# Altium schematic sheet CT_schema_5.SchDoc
size 297 x 173 mm
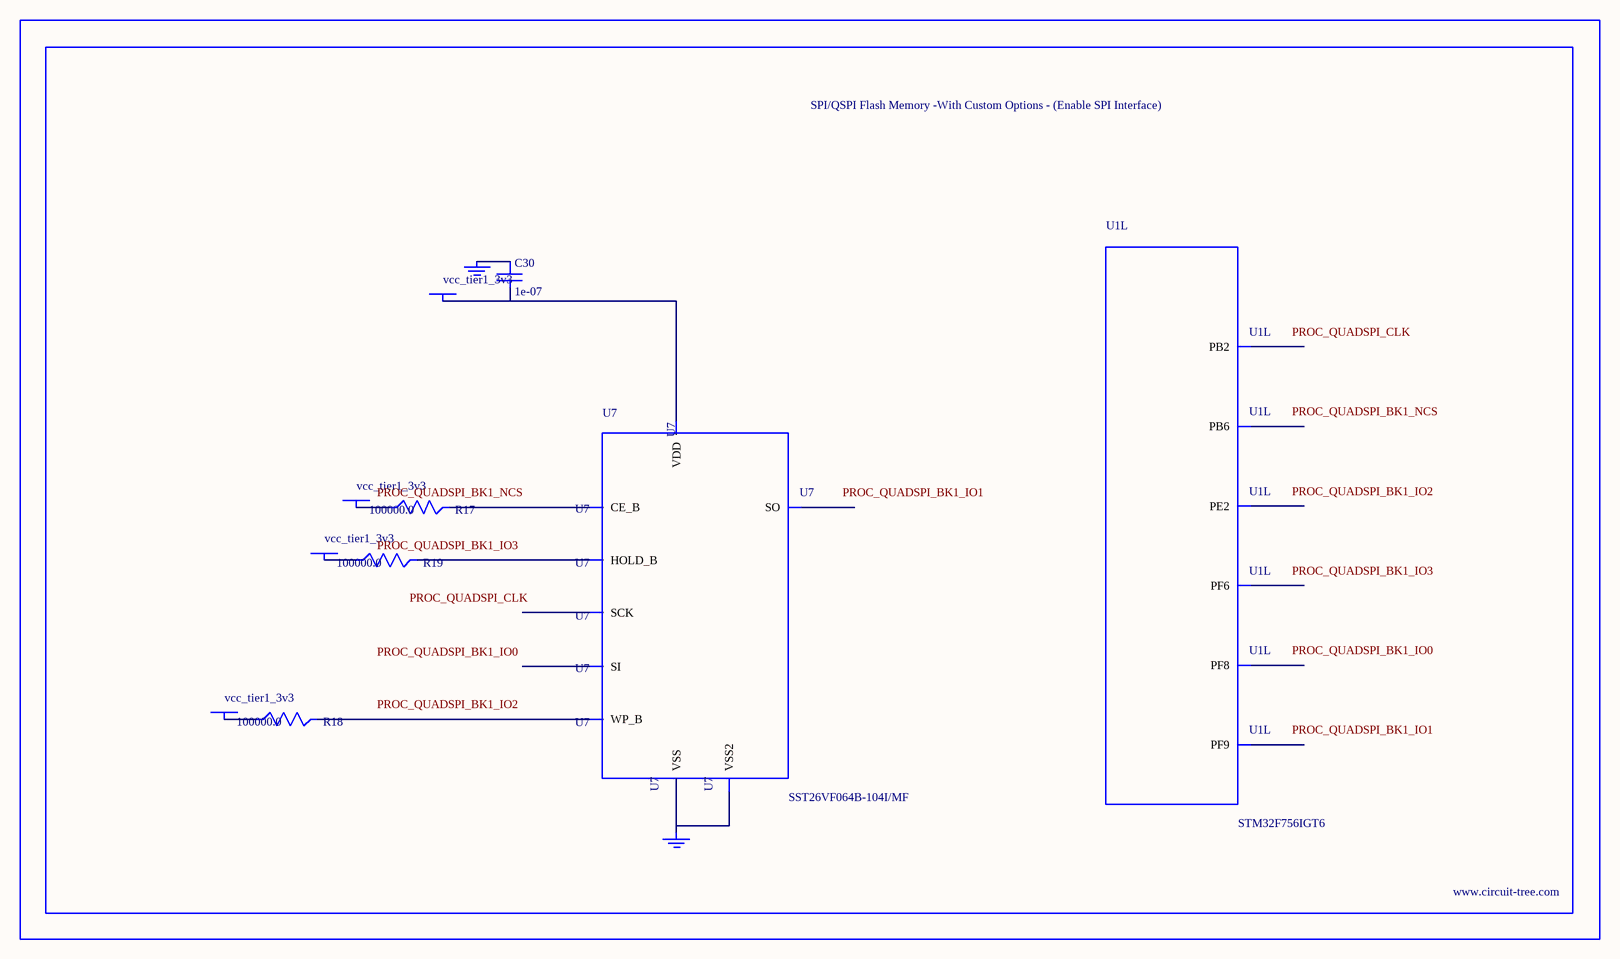
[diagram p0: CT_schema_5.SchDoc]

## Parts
BORDER4  (no value)
C30  1e-07  [C0402]
GND_INSTANCE_4_0  (no value)
GND_INSTANCE_4_1  (no value)
POWER_INSTANCE_4_0  vcc_tier1_3v3
POWER_INSTANCE_4_1  vcc_tier1_3v3
POWER_INSTANCE_4_2  vcc_tier1_3v3
POWER_INSTANCE_4_3  vcc_tier1_3v3
R17  100000.0  [R0603]
R18  100000.0  [R0603]
R19  100000.0  [R0603]
U1  STM32F756IGT6  [LQFP176]  (part L of 14)
U7  SST26VF064B-104I/MF  [WFDN-8]

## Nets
NetC30_1: C30.1 GND_INSTANCE_4_0.0(GND)
NetC30_2: C30.2 POWER_INSTANCE_4_3.0(PWR) U7.8(VDD)
NetGND_INSTANCE_4_1_0: GND_INSTANCE_4_1.0(GND) U7.4(VSS) U7.9(VSS2)
NetPOWER_INSTANCE_4_0_0: POWER_INSTANCE_4_0.0(PWR) R17.1
NetPOWER_INSTANCE_4_1_0: POWER_INSTANCE_4_1.0(PWR) R18.1
NetPOWER_INSTANCE_4_2_0: POWER_INSTANCE_4_2.0(PWR) R19.1
NetR17_2: R17.2 U7.1(CE_B)
NetR18_2: R18.2 U7.3(WP_B)
NetR19_2: R19.2 U7.7(HOLD_B)

Not connected (* = marked no-connect by the designer): U1 1(PE2) 24(PF6) 26(PF8) 27(PF9) 58(PB2) 164(PB6); U7 2(SO) 5(SI) 6(SCK)

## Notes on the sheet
- Labels drawn without touching a wire or pin: PROC_QUADSPI_BK1_IO0, PROC_QUADSPI_BK1_IO1, PROC_QUADSPI_BK1_IO2, PROC_QUADSPI_BK1_IO3, PROC_QUADSPI_BK1_NCS, PROC_QUADSPI_CLK

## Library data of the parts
BORDER4 = BORDER_PAGE4
C30 = C0402C104K3RACTU
GND_INSTANCE_4_0 GND_INSTANCE_4_1 = GND
POWER_INSTANCE_4_0-POWER_INSTANCE_4_3 = PWR
R17-R19 = RC0603JR-07100KL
